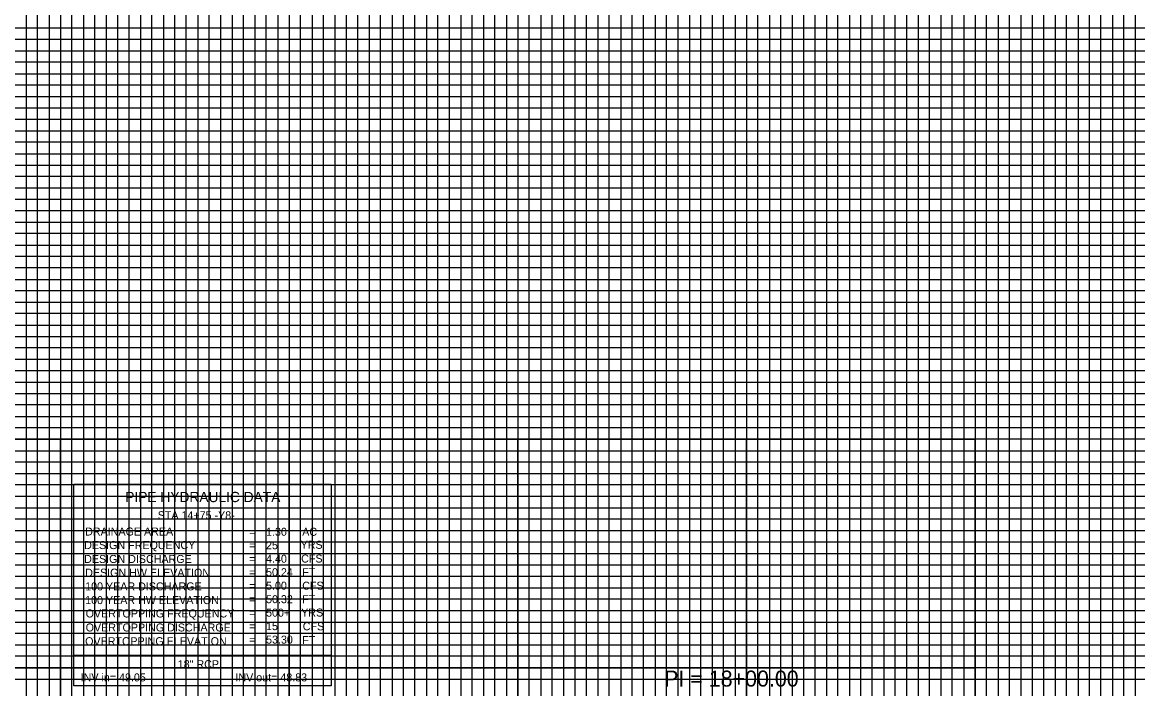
# Model space of a CAD drawing. Extents: x 2345490 to 2445302, y 465165 to 573888.
# Drawn here: x 2382250.1 to 2382737.9, y 541265.3 to 541557 of the extents above; entities that cross this region are included whole.
import ezdxf

# ---------------------------------------------------------------- set-up
doc = ezdxf.new("R2010")
doc.units = 0
for name, color, linetype in [('Old_Level_2', 7, 'Continuous'), ('Old_Level_4', 7, 'Continuous'), ('Old_Level_41', 7, 'Continuous'), ('Old_Level_42', 7, 'Continuous'), ('Old_Level_43', 7, 'Continuous'), ('Old_Level_57', 7, 'Continuous')]:
    doc.layers.add(name, color=color, linetype=linetype)

msp = doc.modelspace()

# ---------------------------------------------------------------- linework, layer by layer
at = {"layer": 'Old_Level_4'}
for p, q in [((2382272.67092, 541354.8205), (2382385.17092, 541354.8205)), ((2382272.67092, 541279.8205), (2382272.67092, 541354.8205)), ((2382385.17092, 541354.8205), (2382385.17092, 541279.8205)), ((2382385.17092, 541279.8205), (2382272.67092, 541279.8205))]:
    msp.add_line(p, q, dxfattribs=at)
msp.add_lwpolyline([(2382272.67092, 541279.8205), (2382385.17092, 541279.8205), (2382385.17092, 541266.6055), (2382272.67092, 541266.6055)], close=True, dxfattribs=at)
at = {"layer": 'Old_Level_41'}
for points in [[(2382216.79875, 542049.5045), (2382266.79875, 542049.5045), (2382266.79875, 541024.5045), (2382316.79875, 541024.5045), (2382316.79875, 542049.5045), (2382366.79875, 542049.5045), (2382366.79875, 541024.5045), (2382416.79875, 541024.5045), (2382416.79875, 542049.5045), (2382466.79875, 542049.5045), (2382466.79875, 541024.5045), (2382516.79875, 541024.5045), (2382516.79875, 542049.5045), (2382566.79875, 542049.5045), (2382566.79875, 541024.5045), (2382616.79875, 541024.5045), (2382616.79875, 542049.5045), (2382666.79875, 542049.5045), (2382666.79875, 541024.5045), (2382716.79875, 541024.5045), (2382716.79875, 542049.5045), (2382766.79875, 542049.5045)], [(2382241.79875, 541024.5045), (2382291.79875, 541024.5045), (2382291.79875, 542049.5045), (2382341.79875, 542049.5045), (2382341.79875, 541024.5045), (2382391.79875, 541024.5045), (2382391.79875, 542049.5045), (2382441.79875, 542049.5045), (2382441.79875, 541024.5045), (2382491.79875, 541024.5045), (2382491.79875, 542049.5045), (2382541.79875, 542049.5045), (2382541.79875, 541024.5045), (2382591.79875, 541024.5045), (2382591.79875, 542049.5045), (2382641.79875, 542049.5045), (2382641.79875, 541024.5045), (2382691.79875, 541024.5045), (2382691.79875, 542049.5045), (2382741.79875, 542049.5045)], [(2383216.79875, 541549.5045), (2381716.79875, 541549.5045), (2381716.79875, 541499.5045), (2383216.79875, 541499.5045)], [(2383216.79875, 541449.5045), (2381716.79875, 541449.5045), (2381716.79875, 541399.5045), (2383216.79875, 541399.5045)], [(2383216.79875, 541374.5045), (2381716.79875, 541374.5045), (2381716.79875, 541424.5045), (2383216.79875, 541424.5045)], [(2383216.79875, 541349.5045), (2381716.79875, 541349.5045), (2381716.79875, 541299.5045), (2383216.79875, 541299.5045)], [(2383216.79875, 541274.5045), (2381716.79875, 541274.5045), (2381716.79875, 541324.5045), (2383216.79875, 541324.5045)]]:
    msp.add_lwpolyline(points, dxfattribs=at)
at = {"layer": 'Old_Level_42'}
msp.add_lwpolyline([(2383216.79875, 541474.5045), (2381716.79875, 541474.5045), (2381716.79875, 541524.5045), (2383216.79875, 541524.5045)], dxfattribs=at)
at = {"layer": 'Old_Level_43'}
for points in [[(2382251.79875, 542049.5045), (2382251.79875, 541024.5045), (2382256.79875, 541024.5045), (2382256.79875, 542049.5045), (2382261.79875, 542049.5045), (2382261.79875, 541024.5045), (2382271.79875, 541024.5045), (2382271.79875, 542049.5045), (2382276.79875, 542049.5045), (2382276.79875, 541024.5045), (2382281.79875, 541024.5045), (2382281.79875, 542049.5045), (2382286.79875, 542049.5045), (2382286.79875, 541024.5045)], [(2382296.79875, 541024.5045), (2382296.79875, 542049.5045)], [(2382301.79875, 542049.5045), (2382301.79875, 541024.5045), (2382306.79875, 541024.5045), (2382306.79875, 542049.5045)], [(2382311.79875, 542049.5045), (2382311.79875, 541024.5045), (2382321.79875, 541024.5045), (2382321.79875, 542049.5045)], [(2382326.79875, 542049.5045), (2382326.79875, 541024.5045), (2382326.79875, 541024.5045), (2382331.79875, 541024.5045), (2382331.79875, 542049.5045)], [(2382336.79875, 542049.5045), (2382336.79875, 541024.5045), (2382346.79875, 541024.5045), (2382346.79875, 542049.5045)], [(2382351.79875, 542049.5045), (2382351.79875, 541024.5045), (2382356.79875, 541024.5045), (2382356.79875, 542049.5045)], [(2382361.79875, 542049.5045), (2382361.79875, 541024.5045), (2382371.79875, 541024.5045), (2382371.79875, 542049.5045)], [(2382376.79875, 542049.5045), (2382376.79875, 541024.5045), (2382381.79875, 541024.5045), (2382381.79875, 542049.5045)], [(2382386.79875, 542049.5045), (2382386.79875, 541024.5045), (2382396.79875, 541024.5045), (2382396.79875, 542049.5045)], [(2382401.79875, 542049.5045), (2382401.79875, 541024.5045), (2382406.79875, 541024.5045), (2382406.79875, 542049.5045)], [(2382411.79875, 542049.5045), (2382411.79875, 541024.5045), (2382421.79875, 541024.5045), (2382421.79875, 542049.5045)], [(2382426.79875, 542049.5045), (2382426.79875, 541024.5045), (2382431.79875, 541024.5045), (2382431.79875, 542049.5045)], [(2382436.79875, 542049.5045), (2382436.79875, 541024.5045), (2382446.79875, 541024.5045), (2382446.79875, 542049.5045)], [(2382451.79875, 542049.5045), (2382451.79875, 541024.5045), (2382456.79875, 541024.5045), (2382456.79875, 542049.5045)], [(2382461.79875, 542049.5045), (2382461.79875, 541024.5045), (2382471.79875, 541024.5045), (2382471.79875, 542049.5045)], [(2382476.79875, 542049.5045), (2382476.79875, 541024.5045)], [(2382476.79875, 541024.5045), (2382481.79875, 541024.5045), (2382481.79875, 542048.9045)], [(2382486.79875, 542048.9045), (2382486.79875, 541024.5045), (2382496.79875, 541024.5045), (2382496.79875, 542049.5045)], [(2382501.79875, 542049.5045), (2382501.79875, 541024.5045), (2382506.79875, 541024.5045), (2382506.79875, 542049.5045)], [(2382511.79875, 542049.5045), (2382511.79875, 541024.5045), (2382521.79875, 541024.5045), (2382521.79875, 542049.5045)], [(2382526.79875, 542049.5045), (2382526.79875, 541024.5045), (2382531.79875, 541024.5045), (2382531.79875, 542049.5045)], [(2382536.79875, 542049.5045), (2382536.79875, 541024.5045), (2382546.79875, 541024.5045), (2382546.79875, 542049.5045)], [(2382551.79875, 542049.5045), (2382551.79875, 541024.5045), (2382556.79875, 541024.5045), (2382556.79875, 542049.5045)], [(2382561.79875, 542049.5045), (2382561.79875, 541024.5045), (2382571.79875, 541024.5045), (2382571.79875, 542049.5045)], [(2382576.79875, 542049.5045), (2382576.79875, 541024.5045), (2382581.79875, 541024.5045), (2382581.79875, 542049.5045)], [(2382586.79875, 542049.5045), (2382586.79875, 541024.5045), (2382596.79875, 541024.5045), (2382596.79875, 542049.5045)], [(2382601.79875, 542049.5045), (2382601.79875, 541024.5045), (2382606.79875, 541024.5045), (2382606.79875, 542049.5045)], [(2382611.79875, 542049.5045), (2382611.79875, 541024.5045), (2382621.79875, 541024.5045), (2382621.79875, 542049.5045)], [(2382626.79875, 542049.5045), (2382626.79875, 541024.5045), (2382631.79875, 541024.5045), (2382631.79875, 542049.5045)], [(2382636.79875, 542049.5045), (2382636.79875, 541024.5045), (2382646.79875, 541024.5045), (2382646.79875, 542049.5045)], [(2382651.79875, 542049.5045), (2382651.79875, 541024.5045), (2382656.79875, 541024.5045), (2382656.79875, 542049.5045)], [(2382661.79875, 542049.5045), (2382661.79875, 541024.5045), (2382671.79875, 541024.5045), (2382671.79875, 542049.5045)], [(2382676.79875, 542049.5045), (2382676.79875, 541024.5045), (2382681.79875, 541024.5045), (2382681.79875, 542049.5045)], [(2382686.79875, 542049.5045), (2382686.79875, 541024.5045), (2382696.79875, 541024.5045), (2382696.79875, 542049.5045)], [(2382701.79875, 542049.5045), (2382701.79875, 541024.5045), (2382706.79875, 541024.5045), (2382706.79875, 542049.5045)], [(2382711.79875, 542049.5045), (2382711.79875, 541024.5045), (2382721.79875, 541024.5045), (2382721.79875, 542049.5045)], [(2382726.79875, 542049.5045), (2382726.79875, 541024.5045), (2382731.79875, 541024.5045), (2382731.79875, 542049.5045)], [(2382736.79875, 542049.5045), (2382736.79875, 541024.5045), (2382746.79875, 541024.5045)], [(2383166.79875, 541554.5045), (2381766.79875, 541554.5045), (2381766.79875, 541544.5045), (2383166.79875, 541544.5045)], [(2383166.79875, 541539.5045), (2381766.79875, 541539.5045), (2381766.79875, 541534.5045), (2383166.79875, 541534.5045)], [(2383166.79875, 541529.5045), (2381766.79875, 541529.5045)], [(2381766.79875, 541519.5045), (2383166.79875, 541519.5045)], [(2383166.79875, 541514.5045), (2381766.79875, 541514.5045), (2381766.79875, 541509.5045), (2383166.79875, 541509.5045)], [(2383166.79875, 541504.5045), (2381766.79875, 541504.5045), (2381766.79875, 541494.5045), (2383166.79875, 541494.5045)], [(2383166.79875, 541489.5045), (2381766.79875, 541489.5045), (2381766.79875, 541484.5045), (2383166.79875, 541484.5045)], [(2383166.79875, 541479.5045), (2381766.79875, 541479.5045), (2381766.79875, 541469.5045), (2383166.79875, 541469.5045)], [(2383166.79875, 541464.5045), (2381766.79875, 541464.5045), (2381766.79875, 541459.5045), (2383166.79875, 541459.5045)], [(2383166.79875, 541454.5045), (2381766.79875, 541454.5045), (2381766.79875, 541444.5045), (2383166.79875, 541444.5045)], [(2383166.79875, 541439.5045), (2381766.79875, 541439.5045), (2381766.79875, 541434.5045), (2383166.79875, 541434.5045)], [(2383166.79875, 541429.5045), (2381766.79875, 541429.5045), (2381766.79875, 541419.5045), (2383166.79875, 541419.5045)], [(2383166.79875, 541414.5045), (2381766.79875, 541414.5045), (2381766.79875, 541409.5045), (2383166.79875, 541409.5045)], [(2383166.79875, 541404.5045), (2381766.79875, 541404.5045), (2381766.79875, 541394.5045), (2383166.79875, 541394.5045)], [(2383166.79875, 541389.5045), (2381766.79875, 541389.5045), (2381766.79875, 541384.5045), (2383166.79875, 541384.5045)], [(2383166.79875, 541379.5045), (2381766.79875, 541379.5045), (2381766.79875, 541369.5045), (2383166.79875, 541369.5045)], [(2383166.79875, 541364.5045), (2381766.79875, 541364.5045), (2381766.79875, 541359.5045), (2383166.79875, 541359.5045)], [(2383166.79875, 541354.5045), (2381766.79875, 541354.5045), (2381766.79875, 541344.5045), (2383166.79875, 541344.5045)], [(2383166.79875, 541339.5045), (2381766.79875, 541339.5045), (2381766.79875, 541334.5045), (2383166.79875, 541334.5045)], [(2383166.79875, 541329.5045), (2381766.79875, 541329.5045), (2381766.79875, 541319.5045), (2383166.79875, 541319.5045)], [(2383166.79875, 541314.5045), (2381766.79875, 541314.5045), (2381766.79875, 541309.5045), (2383166.79875, 541309.5045)], [(2383166.79875, 541304.5045), (2381766.79875, 541304.5045), (2381766.79875, 541294.5045), (2383166.79875, 541294.5045)], [(2383166.79875, 541289.5045), (2381766.79875, 541289.5045), (2381766.79875, 541284.5045), (2383166.79875, 541284.5045)], [(2383166.79875, 541279.5045), (2381766.79875, 541279.5045), (2381766.79875, 541269.5045), (2383166.79875, 541269.5045)]]:
    msp.add_lwpolyline(points, dxfattribs=at)
at = {"layer": 'Old_Level_57'}
for p, q in [((2381716.79925, 541374.50475), (2382666.79875, 541374.50475)), ((2382266.79875, 541024.50475), (2382266.79875, 541374.50475)), ((2382266.79875, 541024.60475), (2382266.79875, 541374.50475)), ((2382366.79875, 541024.50475), (2382366.79875, 541374.50475)), ((2382366.79875, 541024.60475), (2382366.79875, 541374.50475)), ((2382466.79875, 541024.50475), (2382466.79875, 541374.50475)), ((2382466.79875, 541024.60475), (2382466.79875, 541374.50475)), ((2382566.79875, 541024.50475), (2382566.79875, 541374.50475)), ((2382566.79875, 541024.60475), (2382566.79875, 541374.50475)), ((2382666.79875, 541024.50475), (2382666.79875, 541374.50475)), ((2381716.79925, 541324.50475), (2382666.79875, 541324.50475)), ((2381716.79925, 541274.50475), (2382666.79875, 541274.50475))]:
    msp.add_line(p, q, dxfattribs=at)

# ---------------------------------------------------------------- texts
at = {"layer": 'Old_Level_2'}
msp.add_text('PI = 18+00.00', height=7.0000005, dxfattribs=at).set_placement((2382530.77674, 541266.26182))
at = {"layer": 'Old_Level_4'}
for s, height, p in [('PIPE HYDRAULIC DATA', 4.49985, (2382295.07092, 541346.9955)), ('STA 14+75 -Y8-', 3.4998, (2382309.29167, 541339.495)), ('DRAINAGE AREA', 3.49995, (2382277.57092, 541332.3705)), ('1.30', 3.49995, (2382356.68142, 541332.27005)), ('AC', 3.49995, (2382372.49592, 541332.2705)), ('=        ', 3.49995, (2382349.22092, 541332.2705)), ('DESIGN FREQUENCY', 3.49995, (2382277.12092, 541326.4455)), ('=        ', 3.49995, (2382349.22092, 541326.3705)), ('25', 3.49995, (2382356.68142, 541326.3701)), ('YRS', 3.49995, (2382371.79592, 541326.5705)), ('DESIGN DISCHARGE', 3.49995, (2382277.12092, 541320.3705)), ('=        ', 3.49995, (2382349.22092, 541320.4705)), ('4.40', 3.49995, (2382356.68142, 541320.47015)), ('CFS', 3.49995, (2382372.02092, 541320.5455)), ('DESIGN HW ELEVATION', 3.49995, (2382277.57092, 541314.3705)), ('=        ', 3.49995, (2382349.22092, 541314.5705)), ('50.24', 3.49995, (2382356.68142, 541314.5702)), ('FT', 3.49995, (2382372.49592, 541314.5705)), ('100 YEAR DISCHARGE', 3.49995, (2382277.57092, 541308.3705)), ('=        ', 3.49995, (2382349.22092, 541308.6705)), ('5.00', 3.49995, (2382356.68142, 541308.67025)), ('CFS', 3.49995, (2382372.49592, 541308.6705)), ('50.32', 3.49995, (2382356.68142, 541302.7703)), ('FT', 3.49995, (2382372.49592, 541302.7705)), ('100 YEAR HW ELEVATION', 3.49995, (2382277.57092, 541302.3705)), ('=        ', 3.49995, (2382349.22092, 541302.7705)), ('OVERTOPPING FREQUENCY', 3.49995, (2382277.79592, 541296.5205)), ('=        ', 3.49995, (2382349.22092, 541296.8705)), ('500+', 3.49995, (2382356.68142, 541296.87035)), ('YRS', 3.49995, (2382372.02092, 541296.9205)), ('OVERTOPPING DISCHARGE', 3.49995, (2382277.79592, 541290.3955)), ('=        ', 3.49995, (2382349.22092, 541290.9705)), ('15', 3.49995, (2382356.68142, 541290.9704)), ('CFS', 3.49995, (2382372.72092, 541290.8955)), ('OVERTOPPING ELEVATION', 3.49995, (2382277.57092, 541284.3705)), ('=        ', 3.49995, (2382349.22092, 541285.0705)), ('53.30', 3.49995, (2382356.68142, 541285.07045)), ('FT', 3.49995, (2382372.49592, 541284.8705)), ('18" RCP', 3.4998, (2382318.06017, 541274.32325)), ('INV in= 49.05', 3.4998, (2382275.60342, 541268.5325)), ('INV out= 48.83', 3.4998, (2382343.28017, 541268.5325))]:
    msp.add_text(s, height=height, dxfattribs=at).set_placement(p)

doc.saveas('drawing.dxf')
